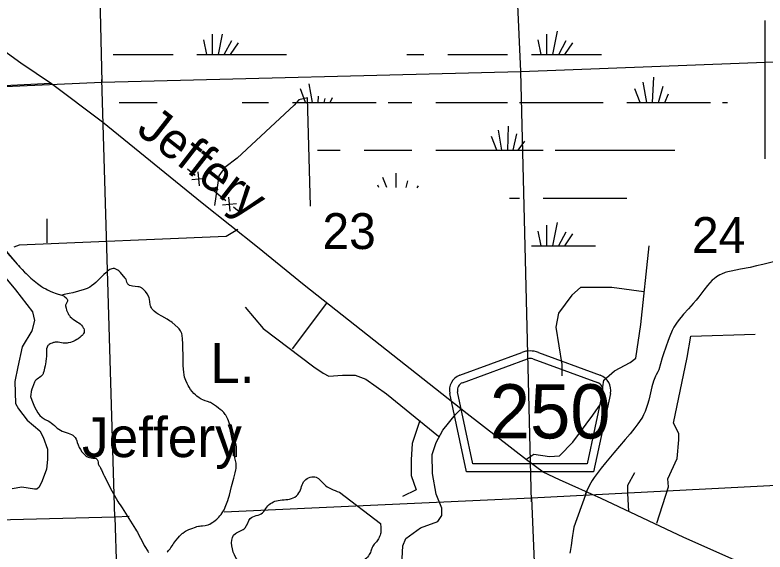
# Model space of a CAD drawing. Extents: x 2480962 to 2688785, y 277103 to 599240.
# Drawn here: x 2538319 to 2547738, y 442588 to 449327 of the extents above; entities that cross this region are included whole.
import ezdxf

# ---------------------------------------------------------------- set-up
doc = ezdxf.new("R2010")
doc.units = 0
for name, color, linetype in [('County Roads Related Text', 7, 'Continuous'), ('County Routes Highway Center Lines', 7, 'Continuous'), ('Lakes and Ponds', 7, 'Continuous'), ('Lakes and Ponds Text', 7, 'Continuous'), ('Level 31', 7, 'Continuous'), ('Level 42', 7, 'Continuous'), ('Local Roads Paved', 7, 'Continuous'), ('Narrow River Creek and Branch and Slough', 7, 'Continuous'), ('Roadshields County Roads', 7, 'Continuous'), ('Roadshields US Highways', 7, 'Continuous'), ('Section Lines', 7, 'Continuous'), ('Section Numbers', 7, 'Continuous'), ('Swamps', 7, 'Continuous'), ('Uninventoried Roads and Features', 7, 'Continuous')]:
    doc.layers.add(name, color=color, linetype=linetype)

msp = doc.modelspace()

# ---------------------------------------------------------------- linework, layer by layer
at = {"layer": 'County Routes Highway Center Lines'}
msp.add_lwpolyline([(2548065.031, 442171.391), (2546720.333, 442769.035), (2545680.203, 443257.494), (2545157.265, 443493.103), (2544950.388, 443590.795), (2544743.512, 443745.952), (2543996.457, 444320.61), (2542508.094, 445498.658), (2541950.677, 445935.397), (2541364.526, 446412.363), (2540669.191, 446964.034), (2539416.437, 447981.178), (2538778.568, 448463.89), (2538393.547, 448722.486), (2538129.205, 448912.123)], dxfattribs=at)
at = {"layer": 'Lakes and Ponds'}
msp.add_line((2542392.778, 443338.744), (2542909.54, 442945.728), dxfattribs=at)
for points in [[(2540773.177, 444464.649), (2540770.933, 444464.753), (2540735.498, 444474.526), (2540704.984, 444484.364), (2540675.687, 444496.749), (2540656.823, 444506.447), (2540632.494, 444521.205), (2540601.498, 444544.195), (2540584.517, 444559.065), (2540565.753, 444577.628), (2540545.14, 444600.927), (2540523.415, 444629.044), (2540504.201, 444657.704), (2540492.752, 444677.107), (2540479.143, 444703.341), (2540463.866, 444738.956), (2540456.57, 444759.628), (2540449.478, 444783.534), (2540442.96, 444811.216), (2540437.528, 444843.317), (2540433.873, 444880.598), (2540431.741, 444928.107), (2540430.807, 444975.637), (2540430.028, 445070.705), (2540428.311, 445134.051), (2540426.343, 445198.279), (2540422.868, 445262.405), (2540417.282, 445305.065), (2540412.246, 445329.401), (2540406.154, 445347.774), (2540397.373, 445364.668), (2540390.244, 445375.218), (2540379.41, 445388.531), (2540363.096, 445405.19), (2540290.567, 445466.481), (2540276.008, 445478.792), (2540260.757, 445490.203), (2540228.647, 445510.91), (2540161.283, 445547.947), (2540117.052, 445573.144), (2540093.044, 445588.996), (2540067.393, 445609.226), (2540054.695, 445621.192), (2540042.04, 445635.025), (2540031.889, 445649.982), (2540024.726, 445666.407), (2540021.249, 445678.005), (2540017.796, 445694.074), (2540007.673, 445760.689), (2540002.771, 445778.972), (2539994.305, 445798.637), (2539976.644, 445827.764), (2539956.526, 445855.1), (2539941.724, 445872.222), (2539920.228, 445893.557), (2539913.324, 445899.085), (2539905.903, 445903.705), (2539889.73, 445910.598), (2539878.144, 445913.761), (2539861.96, 445916.644), (2539794.896, 445923.155), (2539776.956, 445926.754), (2539758.206, 445933.647), (2539749.203, 445938.928), (2539740.519, 445946.05), (2539735.325, 445952.159), (2539731.243, 445959.001), (2539725.328, 445974.285), (2539714.913, 446007.04), (2539710.389, 446015.883), (2539703.445, 446025.193), (2539642.289, 446093.922), (2539621.237, 446114.35), (2539609.037, 446124.408), (2539594.932, 446134.007), (2539578.59, 446141.97), (2539569.774, 446144.695), (2539560.29, 446146.293), (2539550.079, 446146.378), (2539535.961, 446143.555), (2539521.463, 446137.681), (2539511.707, 446132.402), (2539498.726, 446124.057), (2539481.742, 446111.36), (2539460.311, 446093.418), (2539435.334, 446070.684), (2539411.671, 446047.567), (2539365.591, 446001.431), (2539333.632, 445971.746), (2539306.942, 445948.787), (2539279.289, 445926.993), (2539259.72, 445913.533), (2539242.099, 445903.495), (2539223.824, 445895.171), (2539185.781, 445881.722), (2539115.921, 445860.228), (2539045.902, 445840.941), (2538998.913, 445829.979), (2538935.614, 445818.516), (2538907.567, 445810.251)], [(2538907.567, 445810.251), (2538917.562, 445805.977), (2538935.164, 445796.662), (2538946.199, 445789.322), (2538959.841, 445777.698), (2538967.005, 445769.933), (2538974.559, 445759.906), (2538977.762, 445753.335), (2538978.853, 445746.646), (2538978.586, 445742.129), (2538977.206, 445736.05), (2538973.95, 445727.862), (2538956.282, 445694.818), (2538953.489, 445685.493), (2538953.026, 445680.574), (2538953.516, 445675.381), (2538959.659, 445648.781), (2538967.6, 445622.323), (2538974.153, 445604.827), (2538984.771, 445581.753), (2538991.933, 445568.728), (2539001.203, 445554.013), (2539013.216, 445538.641), (2539026.624, 445525.392), (2539036.188, 445517.513), (2539049.536, 445507.924), (2539105.639, 445473.893), (2539121.171, 445463.505), (2539137.913, 445450.167), (2539146.245, 445442.178), (2539154.569, 445432.829), (2539165.537, 445418.289), (2539175.631, 445402.223), (2539181.299, 445391.055), (2539186.85, 445376.062), (2539188.709, 445367.633), (2539189.421, 445358.291), (2539188.108, 445348.182), (2539186.37, 445343.115), (2539178.957, 445328.793), (2539169.459, 445315.035), (2539162.103, 445306.188), (2539151.183, 445294.809), (2539134.953, 445280.399), (2539111.068, 445262.604), (2539096.642, 445253.192), (2539073.604, 445240.267), (2539050.51, 445229.949), (2539035.008, 445224.256), (2539014.123, 445217.834), (2538985.727, 445210.755), (2538974.358, 445208.763), (2538962.89, 445207.785), (2538939.706, 445208.261), (2538924.108, 445209.891), (2538861.242, 445219.086), (2538843.324, 445220.326), (2538822.976, 445219.746), (2538812.203, 445218.302), (2538800.786, 445215.715), (2538784.694, 445210.589), (2538768.792, 445203.973), (2538758.664, 445198.635), (2538746.187, 445190.242), (2538739.766, 445184.741), (2538733.213, 445177.786), (2538726.93, 445168.914), (2538721.591, 445157.493), (2538716.472, 445138.602), (2538713.823, 445119.603), (2538713.063, 445106.896), (2538712.867, 445089.926), (2538713.229, 445067.301), (2538712.849, 445037.244), (2538711.174, 445020.182), (2538704.359, 444973.079), (2538696.806, 444926.064), (2538690.842, 444894.849), (2538681.118, 444853.486), (2538674.395, 444830.022), (2538671.808, 444823.1), (2538668.516, 444816.649), (2538660.094, 444804.971), (2538653.339, 444797.938), (2538643.24, 444789.269), (2538597.801, 444757.534), (2538585.675, 444747.709), (2538573.619, 444735.14), (2538568.26, 444727.655), (2538563.555, 444718.94), (2538549.971, 444686.513), (2538538.334, 444653.676), (2538531.621, 444631.564), (2538523.922, 444601.819), (2538515.799, 444561.713), (2538512.213, 444538.577)], [(2539373.131, 443674.811), (2539383.869, 443659.744), (2539392.944, 443643.993), (2539398.273, 443633.199), (2539404.725, 443618.545), (2539428.65, 443559.289), (2539436.682, 443542.91), (2539534.143, 443356.595), (2539567.78, 443295.074), (2539587.735, 443260.328), (2539611.403, 443221.105), (2539624.325, 443201.107), (2539637.698, 443181.423), (2539664.327, 443141.989), (2539707.166, 443075.041), (2539749.565, 443007.806), (2539833.707, 442872.98), (2539844.815, 442854.612), (2539855.432, 442836.054), (2539875.55, 442798.476), (2539913.875, 442722.177), (2539940.342, 442671.118), (2539956.586, 442642.093), (2539976.66, 442609.203), (2539985.873, 442596.041), (2539996.218, 442583.385)], [(2540228.972, 442587.258), (2540238.188, 442595.653), (2540247.48, 442604.883), (2540256.699, 442614.97), (2540267.625, 442628.657), (2540277.335, 442642.643), (2540295.053, 442670.859), (2540307.168, 442689.317), (2540314.729, 442699.558), (2540340.279, 442732.549), (2540366.393, 442764.99), (2540384.938, 442785.971), (2540396.17, 442797.634), (2540409.718, 442810.612), (2540418.752, 442818.496), (2540428.045, 442825.892), (2540447.327, 442839.358), (2540460.637, 442847.46), (2540478.864, 442857.334), (2540503.849, 442869.148), (2540537.977, 442883.217), (2540583.987, 442900.683), (2540593.196, 442903.885), (2540602.538, 442906.583), (2540621.555, 442910.725), (2540634.426, 442912.77), (2540651.748, 442914.916), (2540674.979, 442917.333), (2540705.839, 442921.171), (2540723.23, 442924.399), (2540742.733, 442929.629), (2540752.923, 442933.278), (2540763.599, 442937.958), (2540784.44, 442948.948), (2540804.278, 442961.182), (2540816.969, 442970.006), (2540833.253, 442982.572), (2540853.886, 443000.697), (2540865.15, 443011.728), (2540877.576, 443024.912), (2540891.222, 443040.704), (2540906.13, 443059.657), (2540921.463, 443080.922), (2540935.429, 443102.471), (2540943.859, 443117.189), (2540953.856, 443137.482), (2540958.871, 443149.516), (2540975.22, 443192.242), (2540990.664, 443235.11), (2541000.176, 443263.907), (2541011.542, 443302.74), (2541039.694, 443407.619), (2541067.381, 443512.589), (2541085.21, 443582.733), (2541094.236, 443618.988)]]:
    msp.add_lwpolyline(points, dxfattribs=at)
for points in [[(2538512.213, 444538.577), (2538696.501, 444251.232), (2538735.067, 444231.937), (2538889.332, 444116.164), (2538985.747, 444077.574), (2539062.88, 444038.983), (2539101.446, 443961.801), (2539159.295, 443846.029), (2539274.994, 443768.847), (2539352.126, 443749.552), (2539372.465, 443675.685), (2539373.131, 443674.811)], [(2541094.236, 443618.988), (2541095.44, 443653.479), (2541095.44, 443703.831), (2541081.063, 443768.569), (2541081.063, 443854.886), (2541066.686, 443991.555), (2541052.309, 444049.099), (2541030.743, 444142.61), (2541016.366, 444185.768), (2540980.424, 444279.279), (2540958.858, 444315.244), (2540872.596, 444394.368), (2540773.177, 444464.649)], [(2542797.454, 442622.547), (2542776.546, 442570.719), (2542672.825, 442456.553), (2542517.243, 442352.766), (2542351.289, 442352.766), (2542226.824, 442321.629), (2542019.382, 442280.115), (2541843.056, 442300.872), (2541677.102, 442404.659), (2541552.636, 442404.659), (2541334.822, 442342.387), (2541075.519, 442549.961), (2541085.891, 442819.808), (2541210.356, 442892.459), (2541272.589, 443006.625), (2541428.171, 443079.276), (2541480.031, 443151.927), (2541625.241, 443234.957), (2541811.939, 443266.093), (2541884.544, 443328.366), (2541957.149, 443484.046), (2542102.359, 443525.561), (2542195.708, 443442.531), (2542392.778, 443338.744)], [(2542909.54, 442945.728), (2542911.384, 442913.217), (2542911.384, 442861.323), (2542911.384, 442830.187), (2542890.64, 442767.915), (2542859.523, 442716.021), (2542828.407, 442684.885), (2542812.125, 442661.219), (2542797.454, 442622.547)]]:
    msp.add_spline(points, degree=3, dxfattribs=at)
at = {"layer": 'Level 31'}
msp.add_lwpolyline([(2541063.156, 443794.816), (2541063.156, 443925.51), (2541020.567, 444124.39), (2541000.693, 444184.055), (2541029.085, 444189.737), (2541077.352, 444007.903), (2541097.227, 443905.621), (2541094.388, 443820.387), (2541094.388, 443791.975), (2541094.388, 443783.452)], close=True, dxfattribs=at)
at = {"layer": 'Local Roads Paved'}
for p, q in [((2535790.608, 448337.297), (2538767.17, 448469.838)), ((2538721.419, 446469.515), (2538721.419, 446769.092)), ((2541802.787, 445136.701), (2542236.868, 445711.401))]:
    msp.add_line(p, q, dxfattribs=at)
for points in [[(2541118.038, 446634.588), (2540971.307, 446548.994), (2538372.932, 446438.946), (2538305.679, 446414.49)], [(2544734.772, 443746.609), (2544835.411, 443813.701), (2545029.979, 443786.864), (2545157.454, 443793.573), (2545325.185, 443968.014), (2545573.427, 444303.476), (2545700.903, 444484.625), (2545700.903, 444659.066), (2545714.321, 444746.286), (2545848.506, 444860.343), (2546043.074, 444967.691), (2546116.876, 445021.365), (2546177.259, 445444.047), (2546284.607, 446430.306)], [(2538183.403, 446047.661), (2538324.021, 445876.474), (2538538.005, 445601.352), (2538562.46, 445491.303), (2538531.891, 445362.913), (2538409.614, 445161.157), (2538354.59, 444910.49), (2538317.907, 444727.075), (2538324.021, 444451.953), (2538360.704, 444384.701), (2538470.753, 444244.083), (2538629.712, 444109.579), (2538672.509, 444030.099), (2538727.533, 443877.254), (2538727.533, 443748.863), (2538715.306, 443626.587), (2538660.281, 443479.855), (2538623.598, 443400.375), (2538593.029, 443375.92), (2538562.46, 443375.92), (2538403.501, 443400.375), (2538281.224, 443382.034)], [(2546217.515, 445853.311), (2545814.96, 445906.985), (2545560.009, 445906.985), (2545419.115, 445906.985), (2545311.767, 445813.055), (2545144.036, 445584.941), (2545110.49, 445410.501), (2545184.291, 444940.854), (2545184.291, 444799.96)], [(2541209.746, 445662.49), (2541435.957, 445393.482), (2542071.795, 444910.49), (2542187.957, 444831.01), (2542261.323, 444794.327), (2542432.51, 444806.555), (2542591.47, 444806.555), (2542725.974, 444757.644), (2542982.754, 444574.229), (2543637.22, 444042.5)], [(2546378.536, 442948.209), (2546526.14, 443404.437), (2546519.431, 443505.076), (2546633.488, 443760.027), (2546653.615, 443994.851), (2546653.615, 444075.362), (2546586.523, 444202.837), (2546760.963, 445028.074), (2546807.928, 445296.444), (2547613.037, 445323.281)], [(2543178.397, 442428.277), (2543190.624, 442666.717), (2543227.307, 442758.424), (2543410.722, 442892.928), (2543630.82, 442972.408), (2543679.73, 443045.774), (2543679.73, 443137.481), (2543606.364, 443314.782), (2543563.568, 443571.562), (2543557.454, 443810.002), (2543606.364, 443962.847), (2543691.958, 444115.693), (2543850.917, 444311.335), (2543918.169, 444378.587)], [(2543404.608, 444237.969), (2543306.787, 443950.619), (2543294.559, 443742.749), (2543294.559, 443547.107), (2543355.698, 443369.806), (2543184.511, 443284.213)], [(2546029.656, 443095.812), (2546016.237, 443323.926), (2546016.237, 443424.565), (2546103.458, 443585.587)]]:
    msp.add_lwpolyline(points, dxfattribs=at)
at = {"layer": 'Narrow River Creek and Branch and Slough'}
for points in [[(2538019.602, 446579.873), (2538346.968, 446201.495), (2538382.734, 446158.827), (2538162.552, 446408.953)], [(2538361.243, 446184.466), (2538380.565, 446163.443), (2538409.993, 446132.378), (2538439.758, 446101.56), (2538458.758, 446082.3), (2538492.644, 446049.579), (2538518.676, 446025.728), (2538558.886, 445990.798), (2538579.58, 445973.615), (2538600.706, 445956.556), (2538617.413, 445943.68), (2538649.54, 445921.173), (2538678.469, 445903.151), (2538704.377, 445888.597), (2538727.48, 445876.747), (2538768.826, 445857.889), (2538800.554, 445845.218), (2538824.727, 445836.487), (2538861.552, 445824.554), (2538908.196, 445810.001)], [(2547845.92, 446230.813), (2547708.338, 446197.492), (2547629.118, 446178.772), (2547549.862, 446160.253), (2547431.152, 446135.786), (2547312.14, 446112.317), (2547269.88, 446102.389), (2547238.65, 446093.433), (2547192.789, 446076.48), (2547170.39, 446066.008), (2547148.404, 446053.948), (2547129.013, 446041.539), (2547097.626, 446017.415), (2547075.854, 445997.621), (2547045.321, 445965.822), (2547016.439, 445932.268), (2546971.077, 445875.538), (2546905.085, 445789.267), (2546871.636, 445746.612), (2546837.037, 445704.898), (2546776.603, 445638.026), (2546715.861, 445571.187), (2546682.844, 445532.873), (2546658.778, 445503.64), (2546624.805, 445458.127), (2546609.156, 445434.296), (2546594.636, 445409.545), (2546573.783, 445369.381), (2546541.68, 445297.65), (2546520.403, 445242.91), (2546463.31, 445076.161), (2546447.677, 445025.738), (2546426.316, 444949.495), (2546402.698, 444874.11), (2546391.285, 444848.357), (2546370.484, 444811.229), (2546360.536, 444792.482), (2546352.187, 444773.085), (2546338.49, 444732.247), (2546318.349, 444659.504), (2546291.837, 444549.06), (2546277.658, 444494.056), (2546261.27, 444439.701), (2546231.231, 444351.652), (2546213.082, 444308.899), (2546202.473, 444288.157), (2546190.557, 444267.957), (2546142.426, 444196.821), (2546104.315, 444145.537), (2546044.653, 444070.926), (2545982.915, 443997.826), (2545911.607, 443915.892), (2545840.431, 443833.885), (2545733.28, 443705.825), (2545680.859, 443640.794), (2545629.358, 443574.776), (2545593.656, 443524.49), (2545569.062, 443485.408), (2545534.842, 443425.084), (2545502.777, 443363.338), (2545497.511, 443352.107), (2545492.809, 443340.625)], [(2545484.468, 443306.156), (2545495.597, 443352.148), (2545484.468, 443306.156), (2545338.258, 442897.216), (2545327.722, 442845.118), (2545318.465, 442792.727), (2545314.25, 442765.02), (2545302.028, 442667.7), (2545295.42, 442619.146), (2545291.507, 442594.971), (2545287.004, 442570.893)]]:
    msp.add_lwpolyline(points, dxfattribs=at)
at = {"layer": 'Roadshields County Roads'}
for p, q in [((2543905.095, 444806.364), (2544684.47, 445092.701)), ((2544891.383, 445092.701), (2545669.405, 444806.861)), ((2543939.581, 444712.499), (2544753.441, 445011.505)), ((2544822.412, 445011.505), (2545634.92, 444712.995)), ((2543989.067, 443594.538), (2543778.51, 444576.71)), ((2544069.901, 443694.539), (2543876.288, 444597.671)), ((2545698.213, 444598.168), (2545504.493, 443694.539)), ((2545795.991, 444577.207), (2545585.327, 443594.538)), ((2545504.493, 443694.538), (2544069.901, 443694.538)), ((2545585.327, 443594.538), (2543989.067, 443594.538))]:
    msp.add_line(p, q, dxfattribs=at)
for centre, radius, start, end in [((2544787.927, 444811.104), 300, 69.8269806, 110.1730139), ((2544787.926, 444917.64), 100, 69.8269876, 110.1729839), ((2543974.066, 444618.633), 200, 110.1729839, 192.0998896), ((2545600.434, 444619.13), 200, 347.9000917, 69.8270083), ((2543974.066, 444618.633), 100, 110.1729839, 192.0998896), ((2545600.434, 444619.129), 100, 347.9000932, 69.8269876)]:
    msp.add_arc(centre, radius, start, end, dxfattribs=at)
at = {"layer": 'Roadshields US Highways'}
msp.add_line((2547737.624, 447522.853), (2547737.624, 449256.229), dxfattribs=at)
at = {"layer": 'Section Lines'}
for p, q in [((2544672.431, 448617.705), (2544439.291, 453895.549)), ((2539284.282, 453748.783), (2539408.867, 448484.921)), ((2544672.43, 448617.705), (2549544.997, 448807.197)), ((2539408.867, 448484.921), (2544672.431, 448617.705)), ((2544805.416, 443218.434), (2544672.43, 448617.705)), ((2533938.726, 448244.263), (2539408.867, 448484.921)), ((2539573.021, 443025.425), (2539407.865, 448518.255)), ((2549646.032, 443513.717), (2544804.359, 443261.354)), ((2544804.359, 443261.354), (2540946.113, 443087.348)), ((2544804.359, 443261.354), (2545043.898, 437969.917)), ((2539573.021, 443025.425), (2534125.418, 442877.178)), ((2539573.021, 443025.425), (2539739.885, 437740.499))]:
    msp.add_line(p, q, dxfattribs=at)
at = {"layer": 'Swamps'}
for p, q in [((2540794.617, 449088.146), (2540794.62, 448829.58)), ((2544994.603, 449088.221), (2544994.606, 448829.656)), ((2545127.507, 449124.47), (2545068.569, 448829.762)), ((2540685.877, 449015.649), (2540723.088, 448829.601)), ((2541036.262, 449003.573), (2540942.256, 448828.983)), ((2544885.863, 449015.724), (2544923.074, 448829.676)), ((2545236.248, 449003.648), (2545142.242, 448829.058)), ((2541120.838, 448979.409), (2541021.52, 448830.426)), ((2545320.824, 448979.485), (2545221.506, 448830.502)), ((2539553.678, 448829.558), (2540003.676, 448829.566)), ((2540003.676, 448829.566), (2540303.675, 448829.571)), ((2543753.664, 448829.633), (2544203.662, 448829.641)), ((2544203.662, 448829.641), (2544503.661, 448829.647)), ((2546325.171, 448229.703), (2546342.407, 448545.782)), ((2546254.171, 448229.752), (2546207.916, 448484.136)), ((2546401.857, 448229.882), (2546460.089, 448433.705)), ((2541969.111, 448229.763), (2541903.639, 448401.631)), ((2546169.097, 448229.839), (2546103.625, 448401.706)), ((2546478.452, 448229.806), (2546527.336, 448338.44)), ((2541803.677, 448229.589), (2542853.673, 448229.608)), ((2543003.673, 448229.611), (2543303.672, 448229.616)), ((2543603.671, 448229.622), (2544203.669, 448229.633)), ((2544203.669, 448229.633), (2544503.668, 448229.638)), ((2544653.667, 448229.641), (2545703.664, 448229.66)), ((2546003.663, 448229.665), (2547053.659, 448229.684)), ((2544431.677, 447629.692), (2544392.283, 447882.93)), ((2544509.839, 447629.649), (2544515.566, 447933.367)), ((2544369.355, 447630.614), (2544303.284, 447803.41)), ((2544576.937, 447629.441), (2544619.822, 447835.295)), ((2544639.133, 447629.134), (2544722.911, 447742.837)), ((2542703.68, 447629.597), (2543303.679, 447629.608)), ((2543603.678, 447629.613), (2544203.676, 447629.624)), ((2544203.676, 447629.624), (2544953.673, 447629.638)), ((2545103.673, 447629.64), (2546603.668, 447629.668)), ((2544953.68, 447029.629), (2546003.676, 447029.648)), ((2544994.629, 446688.187), (2544994.632, 446429.621)), ((2545127.534, 446724.436), (2545068.596, 446429.727)), ((2544885.89, 446615.69), (2544923.101, 446429.642)), ((2545236.275, 446603.614), (2545142.269, 446429.024)), ((2545320.851, 446579.45), (2545221.533, 446430.467)), ((2539753.26, 443033.554), (2539573.02, 443025.425))]:
    msp.add_line(p, q, dxfattribs=at)
for points in [[(2540919.628, 449084.924), (2540868.583, 448829.686)], [(2540603.674, 448829.577), (2541728.464, 448829.597)], [(2543237.735, 448829.624), (2543453.665, 448829.628)], [(2544803.66, 448829.652), (2545684.479, 448829.668)], [(2542054.185, 448229.676), (2542011.785, 448462.867)], [(2542125.185, 448229.627), (2542129.589, 448310.382)], [(2542201.871, 448229.806), (2542215.477, 448277.429)], [(2542278.466, 448229.73), (2542305.853, 448290.588)], [(2539626.207, 448229.55), (2540003.683, 448229.557)], [(2540003.683, 448229.557), (2540105.745, 448229.559)], [(2541171.503, 448229.578), (2541503.678, 448229.584)], [(2547203.659, 448229.687), (2547267.537, 448229.688)], [(2542117.336, 447629.586), (2542403.681, 447629.591)], [(2543102.341, 447340.604), (2543102.343, 447164.005)], [(2542933.19, 447292.271), (2542982.551, 447166.417)], [(2543247.329, 447243.947), (2543226.706, 447161.449)], [(2542872.781, 447195.61), (2542885.232, 447166.42)], [(2543380.234, 447183.537), (2543365.684, 447158.593)], [(2544527.515, 447029.621), (2544653.681, 447029.623)], [(2544803.687, 446429.618), (2545610.792, 446429.632)]]:
    msp.add_lwpolyline(points, dxfattribs=at)
at = {"layer": 'Uninventoried Roads and Features'}
for p, q in [((2540580.208, 447312.206), (2540483.697, 447391.647)), ((2540636.998, 447184.511), (2540619.928, 447360.462)), ((2540540.487, 447263.951), (2540716.438, 447281.021)), ((2540966.249, 446994.445), (2540676.718, 447232.766)), ((2541023.039, 446866.75), (2541005.969, 447042.701)), ((2540926.529, 446946.19), (2541102.479, 446963.26)), ((2541159.269, 446835.565), (2541062.759, 446915.005))]:
    msp.add_line(p, q, dxfattribs=at)
msp.add_lwpolyline([(2542030.349, 446930.048), (2541990.963, 448287.466), (2541881.686, 448262.357), (2541825.154, 448197.682), (2541108.104, 447530.85), (2540952.436, 447414.241), (2540877.464, 447306.794), (2540851.867, 447134.641), (2540824.823, 446937.382)], dxfattribs=at)

# ---------------------------------------------------------------- texts
at = {"layer": 'County Roads Related Text'}
msp.add_text('Jeffery', height=450, rotation=322.1002917, dxfattribs=at).set_placement((2539827.58, 447855.766))
at = {"layer": 'Lakes and Ponds Text'}
msp.add_text('L.', height=500, rotation=0.0289944, dxfattribs=at).set_placement((2540771.375, 444708.741))
at = {"layer": 'Level 42'}
msp.add_text('Jeffery', height=500, rotation=0.0290028, dxfattribs=at).set_placement((2539160.317, 443778.202))
at = {"layer": 'Roadshields County Roads'}
msp.add_text('250', height=680, dxfattribs=at).set_placement((2544281.427, 444012.822))
at = {"layer": 'Section Numbers'}
for s, rotation, p in [('23', 359.9795444, (2542180.039, 446390.32)), ('24', 359.9795472, (2546820.584, 446341.351))]:
    msp.add_text(s, height=450, rotation=rotation, dxfattribs=at).set_placement(p)

doc.saveas('drawing.dxf')
